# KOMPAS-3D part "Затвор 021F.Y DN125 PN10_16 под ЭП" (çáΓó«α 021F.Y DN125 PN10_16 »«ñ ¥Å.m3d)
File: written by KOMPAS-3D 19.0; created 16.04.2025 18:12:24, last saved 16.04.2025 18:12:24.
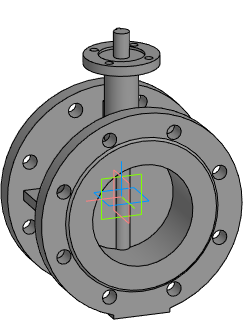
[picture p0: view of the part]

Document properties: Автор: Евгений; Полное имя файла: E:\Dendor Работа Сачек\3D для проекитирвщиков\1.6 Тип 021F.Y Затвор дисковый поворотный фланцевый\stp_Тип 021F.Y Затвор  DN40 PN10_16 под ЭП\Затвор 021F.Y DN125 PN10_16 под ЭП.m3d

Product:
- Part/product: Затвор 021F.Y DN125 PN10_16 под ЭП

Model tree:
1. Операция без истории:1  (labels: Затвор 021F.Y DN125 PN10_16 под ЭП)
